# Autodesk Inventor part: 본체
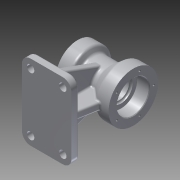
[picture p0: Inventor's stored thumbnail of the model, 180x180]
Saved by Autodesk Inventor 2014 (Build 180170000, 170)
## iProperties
Created: 2015-08
Part Number: 본체
Material: 알루미늄 6061
Document SubType Name: Modeling
Designer: SEC
Density: 2.71 g/cm^3
Appearance: 알루미늄 - 평지
Mass: 1062.8 g
Surface Area: 749.64 cm^2
Volume: 392.179 cm^3
Author: SEC
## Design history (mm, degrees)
sketch "스케치1"
  geometry: L1 (0, 0)-(90, 0); L2 (90, 0)-(90, 40); L3 (90, 40)-(70, 40); L4 (70, 40)-(53.315, 26); L5 (53.315, 26)-(25.196, 26); L6 (25.196, 26)-(20, 35); L7 (20, 35)-(0, 35); L8 (0, 35)-(0, 0)
  constraints: 16 end point, 4 parallel, 1 horizontal, 1 perpendicular
  dimensions: "d8" = 90 distance of L1.start L1.end; "d9" = 20 distance of L6.end L7.end; "d10" = 20 distance of L2.end L3.end; "d11" = 60 deg angle of L5 L6; "d13" = 70 diameter of L7 L1; "d14" = 52 diameter of L5 L1; "d15" = 80 diameter of L3 L1; "d16" = 40 deg angle of L5 L4
revolve "회전1" sketch "스케치1" stored, may be unused: angle "d17" = 90 deg
sketch "스케치2"
  geometry: L1 (0, 0)-(0, -90); L2 (0, -90)-(61, -90); L3 (61, -90)-(61, -78); L4 (61, -78)-(-61, -78); L5 (-61, -78)-(-61, -90); L6 (-61, -90)-(0, -90); C1 r 35 at (0, 0) reference
  constraints: 12 end point, 3 perpendicular, 1 parallel, 1 vertical
  dimensions: "d18" = 90 distance of L1.start L1.end; "d19" = 61 distance of L1.end L2.end; "d20" = 12 distance of L2.end L3.end; "d21" = 122 distance of L3.end L4.end; "d22" = 12 distance of L4.end L5.end
extrude "돌출1" join sketch "스케치2" distance "d23" = 80; taper "d24" = 0 deg
node "작업 평면1"
sketch "스케치3"
  geometry: L1 (61, -78)-(61, -90) reference; L2 (61, -90)-(-61, -90) reference; L3 (-61, -90)-(-61, -78) reference; L4 (-61, -78)-(61, -78) reference; L5 (61, -78)-(61, -90) reference; L6 (61, -90)-(-61, -90) reference; L7 (-61, -90)-(-61, -78) reference; L8 (-61, -78)-(61, -78) reference; L9 (-51, -78)-(-23.638, -2.825); L10 (-51, -78)-(29, -78); L11 (61, -90)-(51, -90); L12 (51, -78)-(23.638, -2.825); L13 (51, -78)-(131, -78); L14 (23.638, -2.825)-(11.975, -18.945); L15 (11.975, -18.945)-(-10.369, -18.945); L16 (-10.369, -18.945)-(-23.638, -2.825); L17 (-51, -78)-(-46.794, -83.109); L18 (-46.794, -83.109)-(36.962, -83.109); L19 (36.962, -83.109)-(51, -78); C1 r 26 at (0, 0) reference; C2 r 26 at (0, 0) reference; 1 further point
  constraints: 22 end point, 4 point on line, 3 parallel, 2 equal length, 2 horizontal, 1 perpendicular
  dimensions: "d26" = 80 distance of L9.start L9.end; "d27" = 70 deg angle of L10 L9; "d28" = 10 distance of L1.end L11.end; "d29" = 80 distance of L12.start L12.end; "d30" = 110 deg angle of L13 L12; "d31" = 35.8848 deg angle of L1 L14; "d32" = 39.4585 deg angle of L1 L16; "d33" = 71.05462 distance between parallel lines of L6 L15; "d34" = 6.89067 distance between parallel lines of L6 L18; "d35" = 68.90093 distance between parallel lines of L16 L17; "d36" = 3.4202 distance from line of L1.start L19; "d37" = 17.57255 distance from line of L1.start L16
extrude "돌출2" join sketch "스케치3" stored distance "d38" = 12; taper "d39" = 0 deg
node "작업 평면2"
node "작업 평면3"
sketch "스케치4"
  geometry: L1 (0, 125)-(0, 55) reference; L2 (0, 55)-(-20, 55) reference; L3 (-20, 55)-(-25.196, 64) reference; L4 (-25.196, 64)-(-34, 64) reference; L5 (-34, 64)-(-34, 12) reference; L6 (-34, 12)-(0, 12) reference; L7 (0, 12)-(0, 0) reference; L8 (0, 0)-(-80, 0) reference; L9 (-80, 0)-(-80, 12) reference; L10 (-80, 12)-(-46, 12) reference; L11 (-46, 12)-(-46, 64) reference; L12 (-46, 64)-(-53.315, 64) reference; L13 (-53.315, 64)-(-70, 50) reference; L14 (-70, 50)-(-90, 50) reference; L15 (-90, 50)-(-90, 130) reference; L16 (-90, 130)-(-70, 130) reference; L17 (-70, 130)-(-53.315, 116) reference; L18 (-53.315, 116)-(-25.196, 116) reference; L19 (-25.196, 116)-(-20, 125) reference; L20 (-20, 125)-(0, 125) reference; L21 (0, 0)-(-10, 0); L22 (-80, 0)-(-70, 0); L23 (-70, 13.351)-(-25, 13.351); L24 (-47.359, 73.9)-(-10, 67.94); L25 (-10, 12)-(-28.69, 4.238); L26 (-28.69, 4.238)-(-60.75, 4.238); L27 (-60.75, 4.238)-(-70, 12); L28 (-70, 12)-(-77.814, 56.316); L29 (-70, 12)-(-25, 12); L30 (-77.814, 56.316)-(-47.359, 73.9); L31 (-10, 12)-(-10, 67.94); 1 further point
  constraints: 22 end point, 4 point on line, 2 horizontal, 2 parallel, 2 perpendicular, 1 equal length
  dimensions: "d40" = 10 distance of L7.end L21.end; "d44" = 45 distance of L27.end L28.end; "d45" = 100 deg angle of L29 L28
extrude "돌출3" join sketch "스케치4" stored distance "d46" = 12; taper "d47" = 0 deg
sketch "스케치5"
  geometry: C1 r 40 at (0, 0) reference; 1 further point
  constraints: 1 coincident
hole "구멍1" sketch "스케치5" at (0, 0) diameter "d48" = 38; stored, may be unused: countersink angle "d52" = 90 deg, drill point angle "d54" = 0 deg; dims "d49" = 6, "d50" = 52, "d51" = 20, "d53" = 23
sketch "스케치6"
  geometry: C1 r 35 at (0, 0) reference; 1 further point
  constraints: 1 coincident
hole "구멍2" sketch "스케치6" at (0, 0) diameter "d55" = 32; stored, may be unused: countersink angle "d59" = 90 deg, drill point angle "d61" = 0 deg; dims "d56" = 6, "d57" = 40, "d58" = 17, "d60" = 100
chamfer "모따기1" distance "d62" = 1; stored, may be unused: second distance "d63" = 2, angle "d64" = 45 deg
fillet "모깎기1" dims "d65" = 14
fillet "모깎기2" dims "d66" = 3
fillet "모깎기3" dims "d67" = 3
fillet "모깎기4" dims "d68" = 3
fillet "모깎기5" dims "d69" = 3
fillet "모깎기6" dims "d70" = 3
fillet "모깎기7" dims "d71" = 3
fillet "모깎기8" dims "d72" = 5
fillet "모깎기9" dims "d73" = 0.3
sketch "스케치7"
  geometry: C1 r 6 at (14, 94); C2 r 6 at (66, 94); C3 r 6 at (66, 0); C4 r 6 at (14, 0); A1 r 14 centre (66, 94) between (80, 94) and (66, 108) reference; A2 r 14 centre (14, 94) between (14, 108) and (0, 94) reference; A3 r 14 centre (14, 0) between (0, 0) and (14, -14) reference; A4 r 14 centre (66, 0) between (66, -14) and (80, 0) reference; 1 further point
  constraints: 4 centre point, 4 coincident
  dimensions: "d74" = 12 diameter of C1; "d75" = 12 diameter of C2; "d76" = 12 diameter of C3; "d77" = 12 diameter of C4
extrude "돌출4" cut sketch "스케치7" distance "d78" = 14; taper "d79" = 0 deg
fillet "모깎기10" dims "d80" = 3
sketch "스케치8"
  geometry: L1 (0, 0)-(0, 33); C1 r 27 at (0, 0) reference; 1 further point
  constraints: 2 end point, 1 coincident, 1 vertical
  dimensions: "d82" = 33 distance of L1.start L1.end
hole "구멍3" sketch "스케치8" at (0, 33) diameter "d83" = 3.242; stored, may be unused: countersink angle "d87" = 90 deg, drill point angle "d89" = 118 deg; dims "d84" = 10, "d85" = 40, "d86" = 17, "d88" = 13
sketch "스케치9"
  geometry: L1 (0, 0)-(0, 27); C1 r 21 at (0, 0) reference; 1 further point
  constraints: 2 end point, 1 coincident, 1 vertical
  dimensions: "d93" = 27 distance of L1.start L1.end
hole "구멍4" sketch "스케치9" at (0, 27) diameter "d94" = 3.242; stored, may be unused: countersink angle "d98" = 90 deg, drill point angle "d100" = 118 deg; dims "d95" = 10, "d96" = 40, "d97" = 17, "d99" = 13
sketch "스케치10"
  geometry: L1 (-58, -78)-(-52.245, -78) reference; L2 (-46.716, -75)-(-9, -75) reference; L3 (-9, -27.568)-(-9, -75) reference; L4 (9, -75)-(9, -27.568) reference; L5 (9, -75)-(46.716, -75) reference; L6 (46.716, -75)-(24.856, -14.94) reference; L7 (-61, -90)-(-61, -81) reference; L8 (61, -90)-(-61, -90) reference; L9 (61, -81)-(61, -90) reference; L10 (52.245, -78)-(58, -78) reference; L11 (-24.856, -14.94)-(-46.716, -75) reference; L12 (-61, -90)-(-24, -90); L13 (58, -90)-(21, -90); L14 (-30, -60)-(-30, -54); L15 (-18, -54)-(-18, -60); L16 (0, 0)-(0, -90); L17 (18, -54)-(18, -60); L18 (30, -60)-(30, -54); C1 r 16 at (0, 0) reference; A1 r 3 centre (-58, -81) between (-58, -78) and (-61, -81) reference; A2 r 29 centre (0, 0) between (-24.856, -14.94) and (-9, -27.568) reference; A3 r 26 centre (0, 0) between (24.985, -7.194) and (-24.985, -7.194) reference; A4 r 29 centre (0, 0) between (9, -27.568) and (24.856, -14.94) reference; A5 r 3 centre (58, -81) between (61, -81) and (58, -78) reference; A6 r 6 centre (-24, -60) between (-30, -60) and (-18, -60); A7 r 6 centre (-24, -54) between (-18, -54) and (-30, -54); A8 r 6 centre (24, -54) between (30, -54) and (18, -54); A9 r 6 centre (24, -60) between (18, -60) and (30, -60)
  constraints: 14 end point, 10 point on circle, 6 symmetric about line, 4 centre point, 4 tangent, 3 point on line, 2 parallel, 1 midpoint, 6 other
  dimensions: "d104" = 37 distance of L7.start L12.end
extrude "돌출5" cut sketch "스케치10" stored distance "d115" = 30; taper "d116" = 0 deg
sketch "스케치12"
  geometry: L1 (71.82, 129.547)-(90, 129.547) reference; L2 (90, 129.547)-(90, 116.325) reference; L3 (89, 115.298)-(70.3, 115.298) reference; L4 (70, 114.99)-(70, 108.028) reference; L5 (67, 104.832)-(17, 104.832) reference; L6 (17, 104.832)-(17, 108.764) reference; L7 (16.7, 109.079)-(1, 109.079) reference; L8 (0, 110.125)-(0, 124.482) reference; L9 (0, 124.482)-(17.113, 124.482) reference; L10 (28.083, 115.298)-(51.496, 115.298) reference; L11 (3, 12)-(7.804, 12) reference; L12 (13, 15)-(31, 15) reference; L13 (31, 15)-(31, 62.432) reference; L14 (31, 62.432)-(28.083, 62.432) reference; L15 (21.732, 53.081)-(13, 53.081) reference; L16 (8.137, 55.518)-(0, 55.518) reference; L17 (0, 55.518)-(0, 69.875) reference; L18 (1, 70.921)-(16.7, 70.921) reference; L19 (17, 71.236)-(17, 75.168) reference; L20 (17, 75.168)-(67, 75.168) reference; L21 (70, 71.972)-(70, 65.01) reference; L22 (70.3, 64.702)-(89, 64.702) reference; L23 (90, 63.675)-(90, 50.453) reference; L24 (90, 50.453)-(78.196, 50.453) reference; L25 (67.483, 15)-(73.293, 47.952) reference; L26 (49, 15)-(67.483, 15) reference; L27 (49, 62.432)-(49, 15) reference; L28 (51.496, 62.432)-(49, 62.432) reference; L29 (73.293, 47.952)-(68.908, 47.952) reference; L30 (0, 0)-(0, 9) reference; L31 (80, 0)-(0, 0) reference; L32 (80, 9)-(80, 0) reference; L33 (72.759, 12)-(77, 12) reference; L34 (13, 53.081)-(13, 15) reference; L35 (0, 0)-(26, 0); L36 (26, 0)-(26, 36); A1 r 3 centre (3, 9) between (3, 12) and (0, 9) reference; A2 r 3 centre (77, 9) between (80, 9) and (77, 12) reference; 8 further points
  constraints: 4 end point, 1 coincident, 1 perpendicular, 1 point on line, 25 other
  dimensions: "d121" = 26 distance of L30.start L35.end; "d122" = 36 distance of L35.end L36.end
feature "엠보싱2" sketch "스케치12" dims "d8" = 90, "d9" = 20, "d10" = 20, "d11" = 60 deg, "d13" = 70, "d14" = 52, "d15" = 80, "d16" = 40 deg, "d123" = 0.5, "d124" = 0
node "솔리드1"
pattern_circular "원형 패턴1" dims angle "d91" = 360 deg
pattern_circular "원형 패턴2" dims angle "d102" = 360 deg
node "절단 모서리 투영1"
node "절단 모서리 투영2"
node "절단 모서리 투영3"
node "절단 모서리 투영4"
node "절단 모서리 투영6"
